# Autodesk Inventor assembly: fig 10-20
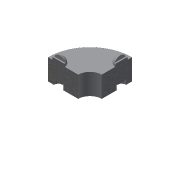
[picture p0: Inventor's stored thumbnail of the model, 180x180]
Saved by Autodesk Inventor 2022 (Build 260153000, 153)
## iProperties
Created: 2002-02
Part Number: fig 10-20
Document SubType Name: Assembly
Designer: ***
Control State: 0
Master: False
Checked Out: False
Shininess: 64.0
Angle Display Precision: 2
Document Length Units: 11269
Document Angle Units: 11279
Document Time Units: 11290
Document Mass Units: 11283
Document Length Units Precision: 3
Document Angle Units Precision: 2
Density: 0.0
Volumn: 0.0
Area: 0.0
PropertySet Name: Model Information
Author: ***
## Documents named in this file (3)
- D:\PROJECTS_2021\Resources\Part Files\c10_Inv_2021_prt\fig 10-20.iam
- D:\PROJECTS_2021\Resources\Part Files\c10_Inv_2021_prt\Screw.ipt
- D:\PROJECTS_2021\Resources\Part Files\c10_Inv_2021_prt\test.ipt
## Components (6 placed, 2 different names)
1. test:1 — Insert:1, Insert:2
2. test:2 — Insert:1
3. Screw:1 — Angle:1, Insert:2
4. Screw:11
5. Screw:12
6. Screw:13
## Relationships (3: Insert 2, Angle 1)
- Insert:1: test:1 ↔ test:2
- Angle:1: Screw:1
- Insert:2: test:1 ↔ Screw:1
